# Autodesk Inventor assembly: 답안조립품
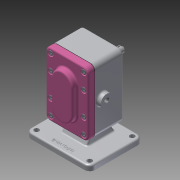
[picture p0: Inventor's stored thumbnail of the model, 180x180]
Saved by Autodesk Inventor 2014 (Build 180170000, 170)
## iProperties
Created: 2020-04
Part Number: 답안조립품
Document SubType Name: Assembly
Designer: kh
Author: kh
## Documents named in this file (11)
- C:\Users\kh\Desktop\700407V1016\답안조립품.iam
- C:\Users\kh\Desktop\700407V1016\본체.ipt
- C:\Users\kh\Desktop\700407V1016\개스킷.ipt
- C:\Users\kh\Desktop\700407V1016\메인축.ipt
- C:\Users\kh\Desktop\700407V1016\베어링부시.ipt
- C:\Users\kh\Desktop\700407V1016\볼트 M5.ipt
- C:\Users\kh\Desktop\700407V1016\서브축.ipt
- C:\Users\kh\Desktop\700407V1016\스퍼기어.ipt
- C:\Users\kh\Desktop\700407V1016\오일 실 16 28 7.ipt
- C:\Users\kh\Desktop\700407V1016\커버.ipt
- C:\Users\kh\Desktop\700407V1016\키 6 x 6 x 18.ipt
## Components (1 placed, 1 different names)
1. 개스킷:1
